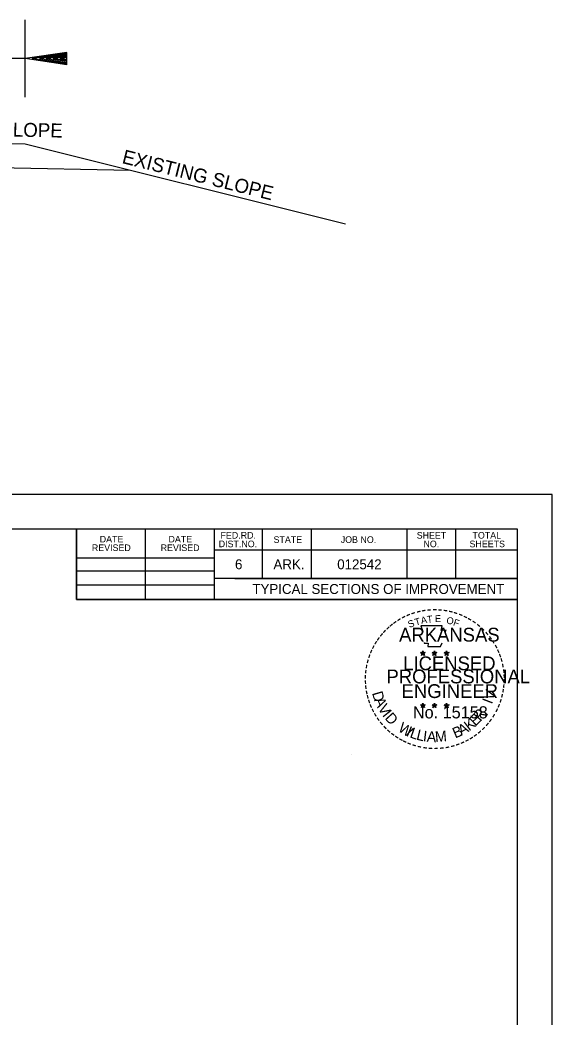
# Model space of a CAD drawing. Extents: x 34757 to 38214, y 51436 to 59430.
# Drawn here: x 36071 to 36457, y 57491 to 58214 of the extents above; entities that cross this region are included whole.
import ezdxf

# ---------------------------------------------------------------- set-up
doc = ezdxf.new("R2010")
doc.units = 0
for name, color, linetype in [('Default', 7, 'Continuous'), ('DSN_DRFT_Junk-No-Plot', 7, 'Continuous'), ('R_Border PE', 7, 'Continuous'), ('R_No Plot', 7, 'Continuous'), ('SHET_Annotations', 7, 'Continuous'), ('SHET_Border-Lines', 7, 'Continuous'), ('SHET_Border-Text', 7, 'Continuous'), ('SHET_Stamp-Prelim', 7, 'Continuous')]:
    doc.layers.add(name, color=color, linetype=linetype)

msp = doc.modelspace()

# ---------------------------------------------------------------- linework, layer by layer
at = {"layer": 'Default'}
for p, q in [((36075.02, 58157.64), (36075.02, 58213.62)), ((36075.02, 58185.63), (35985.02, 58185.63)), ((36105.02, 58190.13), (36075.02, 58185.63)), ((36105.02, 58181.13), (36075.02, 58185.63)), ((36105.02, 58189.38), (36080.03, 58185.63)), ((36105.02, 58181.88), (36080.03, 58185.63)), ((36105.02, 58188.62), (36085.19, 58185.63)), ((36105.02, 58182.65), (36085.19, 58185.63)), ((36105.02, 58187.87), (36090.18, 58185.63)), ((36105.02, 58183.4), (36090.18, 58185.63)), ((36105.02, 58187.1), (36095.27, 58185.63)), ((36105.02, 58184.18), (36095.27, 58185.63)), ((36105.02, 58186.34), (36100.28, 58185.63)), ((36105.02, 58184.93), (36100.28, 58185.63)), ((36105.02, 58181.13), (36105.02, 58190.13)), ((36075.02, 58123.89), (36307.01, 58065.9)), ((35625.02, 58115.39), (36151.12, 58104.87))]:
    msp.add_line(p, q, dxfattribs=at)
msp.add_lwpolyline([(35625.02, 58132.9), (36075.02, 58123.89)], dxfattribs=at)
msp.add_lwpolyline([(34756.64, 57869.61), (34756.64, 56769.61), (36456.64, 56769.61), (36456.64, 57869.61)], close=True, dxfattribs=at)
at = {"layer": 'DSN_DRFT_Junk-No-Plot'}
msp.add_lwpolyline([(34756.64, 57869.61), (34756.64, 56769.61), (36456.64, 56769.61), (36456.64, 57869.61)], close=True, dxfattribs=at)
at = {"layer": 'R_Border PE'}
for p, q in [((36361.35, 57755.17), (36363.1, 57754.61)), ((36361.35, 57755.17), (36362.62, 57754.94)), ((36361.35, 57755.17), (36362.54, 57754.56)), ((36362.02, 57753.13), (36363.1, 57754.61)), ((36362.02, 57753.13), (36362.65, 57754.35)), ((36362.02, 57753.13), (36363.09, 57754.21)), ((36363.1, 57756.44), (36362.89, 57755.18)), ((36364.16, 57753.13), (36363.09, 57754.2)), ((36363.1, 57754.61), (36363.1, 57756.44)), ((36363.1, 57756.44), (36363.34, 57755.19)), ((36364.83, 57755.17), (36363.1, 57754.61)), ((36364.16, 57753.13), (36363.1, 57754.61)), ((36364.83, 57755.17), (36363.4, 57754.92)), ((36364.16, 57753.13), (36363.48, 57754.58)), ((36364.83, 57755.17), (36363.81, 57754.66)), ((36369.7, 57755.17), (36371.45, 57754.61)), ((36369.7, 57755.17), (36370.97, 57754.94)), ((36369.7, 57755.17), (36370.89, 57754.56)), ((36370.37, 57753.13), (36371.45, 57754.61)), ((36370.37, 57753.13), (36371, 57754.35)), ((36370.37, 57753.13), (36371.44, 57754.21)), ((36371.45, 57756.44), (36371.24, 57755.18)), ((36372.51, 57753.13), (36371.44, 57754.2)), ((36371.45, 57754.61), (36371.45, 57756.44)), ((36371.45, 57756.44), (36371.69, 57755.19)), ((36373.18, 57755.17), (36371.45, 57754.61)), ((36372.51, 57753.13), (36371.45, 57754.61)), ((36373.18, 57755.17), (36371.75, 57754.92)), ((36372.51, 57753.13), (36371.83, 57754.58)), ((36373.18, 57755.17), (36372.16, 57754.66)), ((36378.52, 57755.11), (36380.27, 57754.55)), ((36378.52, 57755.11), (36379.79, 57754.88)), ((36378.52, 57755.11), (36379.71, 57754.5)), ((36379.19, 57753.07), (36380.27, 57754.55)), ((36379.19, 57753.07), (36379.82, 57754.29)), ((36379.19, 57753.07), (36380.26, 57754.15)), ((36380.27, 57756.38), (36380.06, 57755.12)), ((36381.33, 57753.07), (36380.26, 57754.14)), ((36380.27, 57754.55), (36380.27, 57756.38)), ((36380.27, 57756.38), (36380.51, 57755.13)), ((36382, 57755.11), (36380.27, 57754.55)), ((36381.33, 57753.07), (36380.27, 57754.55)), ((36382, 57755.11), (36380.57, 57754.86)), ((36381.33, 57753.07), (36380.65, 57754.52)), ((36382, 57755.11), (36380.98, 57754.6)), ((36361.33, 57717.3), (36363.08, 57716.75)), ((36361.33, 57717.3), (36362.6, 57717.08)), ((36361.33, 57717.3), (36362.52, 57716.69)), ((36362, 57715.26), (36363.08, 57716.75)), ((36362, 57715.26), (36362.63, 57716.48)), ((36362, 57715.26), (36363.07, 57716.35)), ((36363.08, 57718.57), (36362.87, 57717.31)), ((36364.14, 57715.26), (36363.07, 57716.33)), ((36363.08, 57716.75), (36363.08, 57718.57)), ((36363.08, 57718.57), (36363.32, 57717.32)), ((36364.81, 57717.3), (36363.08, 57716.75)), ((36364.14, 57715.26), (36363.08, 57716.75)), ((36364.81, 57717.3), (36363.38, 57717.06)), ((36364.14, 57715.26), (36363.46, 57716.72)), ((36364.81, 57717.3), (36363.79, 57716.79)), ((36369.68, 57717.3), (36371.42, 57716.75)), ((36369.68, 57717.3), (36370.94, 57717.08)), ((36369.68, 57717.3), (36370.86, 57716.69)), ((36370.34, 57715.26), (36371.42, 57716.75)), ((36370.34, 57715.26), (36370.97, 57716.48)), ((36370.34, 57715.26), (36371.41, 57716.35)), ((36371.42, 57718.57), (36371.22, 57717.31)), ((36372.49, 57715.26), (36371.41, 57716.33)), ((36371.42, 57716.75), (36371.42, 57718.57)), ((36371.42, 57718.57), (36371.67, 57717.32)), ((36373.16, 57717.3), (36371.42, 57716.75)), ((36372.49, 57715.26), (36371.42, 57716.75)), ((36373.16, 57717.3), (36371.73, 57717.06)), ((36372.49, 57715.26), (36371.8, 57716.72)), ((36373.16, 57717.3), (36372.14, 57716.79)), ((36378.51, 57717.25), (36380.26, 57716.7)), ((36378.51, 57717.25), (36379.78, 57717.03)), ((36378.51, 57717.25), (36379.7, 57716.64)), ((36379.18, 57715.21), (36380.26, 57716.7)), ((36379.18, 57715.21), (36379.81, 57716.43)), ((36379.18, 57715.21), (36380.25, 57716.3)), ((36380.26, 57718.52), (36380.05, 57717.26)), ((36381.32, 57715.21), (36380.25, 57716.28)), ((36380.26, 57716.7), (36380.26, 57718.52)), ((36380.26, 57718.52), (36380.5, 57717.27)), ((36381.99, 57717.25), (36380.26, 57716.7)), ((36381.32, 57715.21), (36380.26, 57716.7)), ((36381.99, 57717.25), (36380.56, 57717.01)), ((36381.32, 57715.21), (36380.64, 57716.67)), ((36381.99, 57717.25), (36380.97, 57716.74))]:
    msp.add_line(p, q, dxfattribs=at)
for points in [[(36361.56, 57774.56), (36362.9, 57770.42)], [(36379.11, 57769.95), (36379.82, 57771.37), (36376.4, 57771.25), (36377.14, 57774.56), (36361.56, 57774.56)], [(36364.02, 57762.44), (36364.02, 57762.01), (36366.83, 57761.91), (36366.56, 57759.55), (36375.91, 57759.55), (36376.92, 57762.23)], [(36363.1, 57756.44), (36364.16, 57753.13), (36361.35, 57755.17), (36364.83, 57755.17), (36362.02, 57753.13), (36363.1, 57756.44)], [(36371.45, 57756.44), (36372.51, 57753.13), (36369.7, 57755.17), (36373.18, 57755.17), (36370.37, 57753.13), (36371.45, 57756.44)], [(36380.27, 57756.38), (36381.33, 57753.07), (36378.52, 57755.11), (36382, 57755.11), (36379.19, 57753.07), (36380.27, 57756.38)], [(36363.08, 57718.57), (36364.14, 57715.26), (36361.33, 57717.3), (36364.81, 57717.3), (36362, 57715.26), (36363.08, 57718.57)], [(36371.42, 57718.57), (36372.49, 57715.26), (36369.68, 57717.3), (36373.16, 57717.3), (36370.34, 57715.26), (36371.42, 57718.57)], [(36380.26, 57718.52), (36381.32, 57715.21), (36378.51, 57717.25), (36381.99, 57717.25), (36379.18, 57715.21), (36380.26, 57718.52)]]:
    msp.add_lwpolyline(points, dxfattribs=at)
for centre, radius in [((36363.09, 57754.61), 0.861), ((36363.09, 57754.61), 0.723), ((36363.09, 57754.61), 0.579), ((36363.09, 57754.61), 0.495), ((36363.09, 57754.61), 0.374), ((36363.09, 57754.61), 0.248), ((36363.09, 57754.61), 0.148), ((36371.44, 57754.61), 0.861), ((36371.44, 57754.61), 0.723), ((36371.44, 57754.61), 0.579), ((36371.44, 57754.61), 0.495), ((36371.44, 57754.61), 0.374), ((36371.44, 57754.61), 0.248), ((36371.44, 57754.61), 0.148), ((36380.26, 57754.55), 0.861), ((36380.26, 57754.55), 0.723), ((36380.26, 57754.55), 0.579), ((36380.26, 57754.55), 0.495), ((36380.26, 57754.55), 0.374), ((36380.26, 57754.55), 0.248), ((36380.26, 57754.55), 0.148), ((36363.07, 57716.74), 0.861), ((36363.07, 57716.74), 0.723), ((36363.07, 57716.74), 0.579), ((36363.07, 57716.74), 0.495), ((36363.07, 57716.74), 0.374), ((36363.07, 57716.74), 0.248), ((36363.07, 57716.74), 0.148), ((36371.42, 57716.74), 0.861), ((36371.42, 57716.74), 0.723), ((36371.42, 57716.74), 0.579), ((36371.42, 57716.74), 0.495), ((36371.42, 57716.74), 0.374), ((36371.42, 57716.74), 0.248), ((36371.42, 57716.74), 0.148), ((36380.25, 57716.69), 0.861), ((36380.25, 57716.69), 0.723), ((36380.25, 57716.69), 0.579), ((36380.25, 57716.69), 0.495), ((36380.25, 57716.69), 0.374), ((36380.25, 57716.69), 0.248), ((36380.25, 57716.69), 0.148)]:
    msp.add_circle(centre, radius, dxfattribs=at)
at = {"layer": 'R_No Plot'}
msp.add_line((36311.1, 57681.61), (36311.1, 57681.61), dxfattribs=at)
at = {"layer": 'SHET_Border-Lines'}
for p, q in [((36112.18, 57793.66), (36112.18, 57844.61)), ((36162.01, 57793.66), (36162.01, 57844.61)), ((36211.83, 57844.61), (36211.83, 57793.66)), ((36246.72, 57844.61), (36246.72, 57808.82)), ((36282.11, 57844.61), (36282.11, 57808.82)), ((36351.37, 57844.61), (36351.37, 57808.82)), ((36386.76, 57844.61), (36386.76, 57808.82)), ((36431.64, 57829.45), (36211.83, 57829.45)), ((36431.64, 57829.55), (36431.64, 57829.55)), ((36112.18, 57823.88), (36211.83, 57823.88)), ((36112.18, 57814.29), (36211.83, 57814.29)), ((36431.64, 57808.82), (36211.83, 57808.82)), ((36226.93, 57808.82), (36431.64, 57808.82)), ((36112.18, 57804.29), (36211.83, 57804.29)), ((36431.64, 57793.66), (36112.18, 57793.66))]:
    msp.add_line(p, q, dxfattribs=at)
for points in [[(34756.64, 56769.61), (36456.64, 56769.61), (36456.64, 57869.61), (34756.64, 57869.61)], [(34781.64, 56794.61), (36431.64, 56794.61), (36431.64, 57844.61), (34781.64, 57844.61)], [(36112.18, 57793.66), (36431.64, 57793.66), (36431.64, 57844.61), (36112.18, 57844.61)]]:
    msp.add_lwpolyline(points, close=True, dxfattribs=at)
at = {"layer": 'SHET_Stamp-Prelim'}
msp.add_lwpolyline([(36321.64, 57793.62), (36321.83, 57793.62), (36321.83, 57793.66), (36321.64, 57793.66)], close=True, dxfattribs=at)

# ---------------------------------------------------------------- texts
at = {"layer": 'Default'}
for rotation, p in [(358.77556, (35989.95, 58130.74)), (345.96318, (36144.53, 58109.99))]:
    msp.add_text('EXISTING SLOPE', height=10.125, rotation=rotation, dxfattribs=at).set_placement(p)
at = {"layer": 'R_Border PE'}
for s, height, rotation, p in [('-', 8, 10.21935, (36362.43, 57782.21)), ('-', 8, 5.89682, (36366.08, 57782.76)), ('-', 8, 0.18623, (36369.94, 57783.12)), ('-', 8, 357.74304, (36373.55, 57783.05)), ('-', 8, 352.16172, (36377.27, 57782.77)), ('-', 8, 34.06357, (36345.97, 57775.41)), ('-', 8, 28.79182, (36348.96, 57777.26)), ('-', 8, 24.30721, (36352.12, 57778.85)), ('S', 5, 21.59401, (36353.33, 57772.95)), ('-', 8, 19.17608, (36355.29, 57780.19)), ('T', 5, 16.4036, (36357.9, 57774.6)), ('-', 8, 13.63015, (36359.04, 57781.4)), ('A', 5, 11.21318, (36362.03, 57775.86)), ('T', 5, 6.02276, (36366.27, 57776.69)), ('E', 5, 0.83234, (36371.8, 57777.24)), ('O', 5, 350.4515, (36379.82, 57776.19)), ('-', 8, 347.20489, (36380.87, 57782.2)), ('F', 5, 340.07066, (36384.59, 57775.05)), ('-', 8, 342.3362, (36384.04, 57781.43)), ('-', 8, 337.85509, (36387.72, 57780.31)), ('-', 8, 334.12109, (36390.87, 57778.96)), ('-', 8, 329.64089, (36393.77, 57777.54)), ('-', 8, 48.42305, (36336.3, 57767.07)), ('-', 8, 42.96224, (36338.54, 57769.46)), ('-', 8, 38.95066, (36340.7, 57771.55)), ('-', 8, 36.23174, (36343.08, 57773.44)), ('-', 8, 325.86266, (36396.98, 57775.74)), ('-', 8, 320.52971, (36400.03, 57773.61)), ('-', 8, 315.57859, (36403.03, 57771.17)), ('-', 8, 54.23247, (36332.22, 57761.81)), ('-', 8, 50.61418, (36334.28, 57764.64)), ('-', 8, 309.87973, (36405.87, 57768.42)), ('-', 8, 306.65218, (36408.5, 57765.41)), ('-', 8, 67.77427, (36327.73, 57753.05)), ('-', 8, 62.87135, (36329.03, 57756.1)), ('-', 8, 58.07063, (36330.59, 57759.17)), ('-', 7, 303.67529, (36410.93, 57762.57)), ('-', 8, 299.66835, (36412.52, 57759.53)), ('-', 8, 294.66279, (36414.14, 57756.47)), ('-', 8, 75.46096, (36325.65, 57746.33)), ('-', 8, 72.39447, (36326.64, 57749.9)), ('-', 8, 290.57283, (36415.43, 57753.59)), ('-', 8, 285.12326, (36416.6, 57750.69)), ('-', 8, 85.18634, (36324.61, 57739.31)), ('-', 8, 81.20126, (36324.99, 57742.76)), ('-', 8, 280.54934, (36417.6, 57746.98)), ('-', 8, 276.59616, (36418.41, 57743.14)), ('-', 8, 89.06224, (36324.49, 57735.8)), ('-', 8, 274.33011, (36418.71, 57739.53)), ('-', 8, 269.94067, (36418.88, 57736.37)), ('-', 8, 94.19588, (36324.66, 57732.18)), ('-', 8, 98.94793, (36325.02, 57728.84)), ('V', 7.7, 72.65729, (36414.1, 57720.07)), ('-', 8, 260.99529, (36418.43, 57729.77)), ('-', 8, 263.5172, (36418.78, 57733.04)), ('-', 8, 101.71495, (36325.7, 57725.18)), ('-', 8, 105.45785, (36326.51, 57722.2)), ('-', 8, 109.08742, (36327.58, 57719.05)), ('D', 7.7, 286.28478, (36326.14, 57725.87)), ('A', 7.7, 292.78351, (36327.61, 57720.86)), ('I', 7.7, 69.03009, (36412.99, 57717.37)), ('-', 8, 252.86809, (36416.97, 57722.78)), ('-', 8, 255.7626, (36417.88, 57726.38)), ('-', 8, 114.06432, (36328.85, 57716.07)), ('-', 8, 115.72885, (36330.38, 57712.98)), ('V', 7.7, 300.79357, (36330.18, 57714.96)), ('I', 7.7, 308.35023, (36333.33, 57709.78)), ('R', 7.7, 50.36514, (36404.74, 57704.93)), ('-', 8, 244.61971, (36414.55, 57716.27)), ('-', 8, 247.88866, (36415.86, 57719.41)), ('-', 8, 120.44712, (36332.16, 57710.05)), ('-', 8, 125.89344, (36334.18, 57707.24)), ('D', 7.7, 311.97742, (36335.08, 57707.45)), ('K', 7.7, 36.91429, (36396.53, 57697.94)), ('E', 7.7, 44.01755, (36401.07, 57701.39)), (',', 7.7, 57.4684, (36408.36, 57709.34)), ('-', 8, 233.84524, (36410.57, 57709.24)), ('-', 8, 239.07125, (36412.58, 57712.51)), ('-', 8, 130.71812, (36336.49, 57704.48)), ('-', 8, 134.22381, (36339.07, 57701.76)), ('-', 8, 138.93382, (36341.7, 57699.44)), ('W', 7.7, 328.07311, (36344.48, 57698.62)), ('I', 7.7, 336.6877, (36350.41, 57695.07)), ('L', 7.7, 340.3149, (36353.06, 57693.85)), ('L', 7.7, 346.66249, (36357.86, 57692.13)), ('B', 7.7, 22.8589, (36386.46, 57692.88)), ('A', 7.7, 28.90423, (36390.94, 57694.75)), ('-', 8, 225.76533, (36406.02, 57703.59)), ('-', 8, 231.25377, (36408.42, 57706.41)), ('-', 8, 144.64634, (36344.48, 57697.41)), ('-', 8, 148.08978, (36347.28, 57695.55)), ('-', 8, 151.57039, (36350.18, 57693.93)), ('I', 7.7, 353.01009, (36362.82, 57690.95)), ('A', 7.7, 356.63729, (36365.7, 57690.52)), ('M', 7.7, 4.64735, (36372.13, 57690.23)), ('-', 8, 207.35684, (36395.21, 57695.02)), ('-', 8, 212.24909, (36398, 57696.75)), ('-', 8, 215.73633, (36400.67, 57698.69)), ('-', 8, 221.08509, (36403.41, 57701.05)), ('-', 8, 154.60019, (36352.79, 57692.69)), ('-', 8, 158.56121, (36355.91, 57691.42)), ('-', 8, 162.79826, (36359.34, 57690.36)), ('-', 8, 167.55551, (36362.92, 57689.54)), ('-', 8, 173.11546, (36366.78, 57688.99)), ('-', 8, 176.51827, (36370.52, 57688.72)), ('-', 8, 181.59176, (36374.24, 57688.82)), ('-', 8, 185.81666, (36378.28, 57689.2)), ('-', 8, 191.28576, (36381.96, 57689.86)), ('-', 8, 195.47429, (36385.61, 57690.85)), ('-', 8, 199.46435, (36388.93, 57692.04)), ('-', 8, 204.25161, (36392.09, 57693.43))]:
    msp.add_text(s, height=height, rotation=rotation, dxfattribs=at).set_placement(p)
for s, height, p in [('ARKANSAS', 10, (36345.82, 57763.12)), ('LICENSED', 10, (36348.81, 57742.37)), ('PROFESSIONAL', 10, (36336.69, 57732.85)), ('ENGINEER', 10, (36347.62, 57722.23)), ('No. 15158', 8.785, (36355.83, 57707.47)), ('AAMU', 0.0001, (36371.09, 57690.2))]:
    msp.add_text(s, height=height, dxfattribs=at).set_placement(p)
at = {"layer": 'SHET_Annotations'}
for s, p in [('6', (36226.93, 57815.54)), ('ARK.', (36254.8, 57815.54)), ('012542', (36301.01, 57815.54)), ('TYPICAL SECTIONS OF IMPROVEMENT', (36239.56, 57797.64))]:
    msp.add_text(s, height=7.2, dxfattribs=at).set_placement(p)
at = {"layer": 'SHET_Border-Text'}
for s, p in [('DATE', (36128.93, 57834.96)), ('DATE', (36178.76, 57834.96)), ('FED.RD.', (36216.44, 57837.75)), ('STATE', (36254.89, 57834.63)), ('JOB NO.', (36303.56, 57834.63)), ('SHEET', (36358.59, 57837.75)), ('TOTAL', (36399, 57837.75)), ('REVISED', (36123.25, 57828.72)), ('REVISED', (36173.08, 57828.72)), ('DIST.NO.', (36215.14, 57831.51)), ('NO.', (36363.48, 57831.51)), ('SHEETS', (36396.85, 57831.51))]:
    msp.add_text(s, height=4.8, dxfattribs=at).set_placement(p)
at = {"layer": 'SHET_Stamp-Prelim'}
for s, height, p in [('PRELIMINARY', 0.013, (36321.66, 57793.64)), ('SUBJECT TO REVISION', 0.009, (36321.67, 57793.63))]:
    msp.add_text(s, height=height, dxfattribs=at).set_placement(p)

doc.saveas('drawing.dxf')
